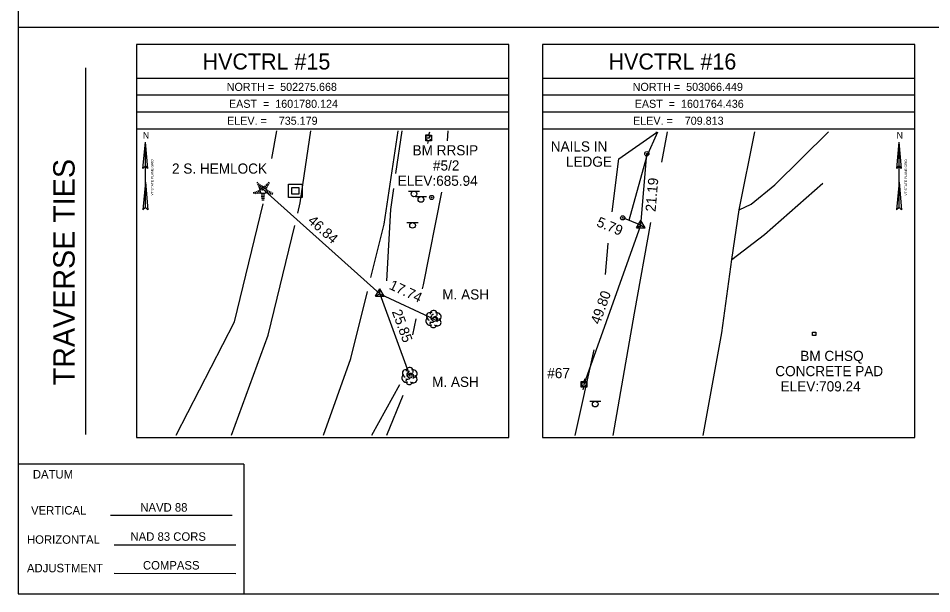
# Model space of a CAD drawing. Extents: x 1598730 to 1599370, y 501440 to 502728.
# Drawn here: x 1598729.5 to 1598999.5, y 501873 to 502042.9 of the extents above; entities that cross this region are included whole.
import ezdxf

# ---------------------------------------------------------------- set-up
doc = ezdxf.new("R2010")
doc.units = 0
for name, color, linetype in [('C_C', 7, 'Continuous'), ('CBP', 7, 'Continuous'), ('CPBM', 7, 'Continuous'), ('CPSM', 7, 'Continuous'), ('Default', 7, 'Continuous'), ('DS', 7, 'Continuous'), ('L_C', 7, 'Continuous'), ('LABL', 7, 'Continuous'), ('LARO', 7, 'Continuous'), ('LAWA', 7, 'Continuous'), ('LTC', 7, 'Continuous'), ('LTD', 7, 'Continuous'), ('LW', 7, 'Continuous'), ('NBL1', 7, 'Continuous'), ('NBL2', 7, 'Continuous'), ('NNA_P', 7, 'Continuous'), ('PET', 7, 'Continuous'), ('RDF', 7, 'Continuous'), ('RGR', 7, 'Continuous'), ('SSGN', 7, 'Continuous'), ('U_C', 7, 'Continuous'), ('UP', 7, 'Continuous'), ('UPGW', 7, 'Continuous')]:
    doc.layers.add(name, color=color, linetype=linetype)

msp = doc.modelspace()

# ---------------------------------------------------------------- linework, layer by layer
at = {"layer": 'CBP'}
for centre, radius in [((1598915.32, 502002.92), 0.625), ((1598915.32, 502002.92), 0.0833), ((1598801.5, 501992.81), 0.625), ((1598801.5, 501992.81), 0.0833), ((1598908.2, 501984), 0.625), ((1598908.2, 501984), 0.0833), ((1598852.47, 501954.04), 0.625), ((1598852.47, 501954.04), 0.0833), ((1598845.28, 501937.29), 0.625), ((1598845.28, 501937.29), 0.0833), ((1598896.76, 501934.9), 0.625), ((1598896.76, 501934.9), 0.0833)]:
    msp.add_circle(centre, radius, dxfattribs=at)
at = {"layer": 'CPBM'}
for p, q in [((1598850.03, 502007.56), (1598850.03, 502008.56)), ((1598850.03, 502008.56), (1598851.03, 502008.56)), ((1598851.03, 502007.56), (1598850.03, 502007.56)), ((1598850.53, 502008.06), (1598850.53, 502008.06)), ((1598850.53, 502008.06), (1598850.53, 502008.06)), ((1598851.03, 502008.56), (1598851.03, 502007.56)), ((1598964.3, 501949.26), (1598964.3, 501950.26)), ((1598964.3, 501950.26), (1598965.3, 501950.26)), ((1598965.3, 501949.26), (1598964.3, 501949.26)), ((1598964.8, 501949.76), (1598964.8, 501949.76)), ((1598964.8, 501949.76), (1598964.8, 501949.76)), ((1598965.3, 501950.26), (1598965.3, 501949.26))]:
    msp.add_line(p, q, dxfattribs=at)
at = {"layer": 'CPSM'}
for p, q in [((1598912.3, 501981.07), (1598913.55, 501983.23)), ((1598912.3, 501981.07), (1598913.55, 501981.79)), ((1598912.3, 501981.07), (1598914.8, 501981.07)), ((1598914.8, 501981.07), (1598913.55, 501983.23)), ((1598913.55, 501981.79), (1598913.55, 501983.23)), ((1598913.55, 501981.79), (1598913.55, 501981.79)), ((1598913.55, 501981.79), (1598914.8, 501981.07)), ((1598835.14, 501960.83), (1598836.39, 501963)), ((1598837.64, 501960.83), (1598836.39, 501963)), ((1598836.39, 501961.56), (1598836.39, 501963)), ((1598835.14, 501960.83), (1598836.39, 501961.56)), ((1598835.14, 501960.83), (1598837.64, 501960.83)), ((1598836.39, 501961.56), (1598836.39, 501961.56)), ((1598836.39, 501961.56), (1598837.64, 501960.83))]:
    msp.add_line(p, q, dxfattribs=at)
at = {"layer": 'Default'}
for p, q in [((1598913.55, 501981.79), (1598915.32, 502002.92)), ((1598801.5, 501992.81), (1598836.39, 501961.56)), ((1598913.55, 501981.79), (1598908.2, 501984)), ((1598896.76, 501934.9), (1598913.55, 501981.79)), ((1598836.39, 501961.56), (1598852.47, 501954.04)), ((1598836.39, 501961.56), (1598845.28, 501937.29))]:
    msp.add_line(p, q, dxfattribs=at)
at = {"layer": 'DS'}
for p, q in [((1598809.42, 501993.97), (1598813.42, 501993.97)), ((1598809.42, 501989.97), (1598809.42, 501993.97)), ((1598810.42, 501990.97), (1598810.42, 501992.97)), ((1598810.42, 501992.97), (1598812.42, 501992.97)), ((1598811.42, 501991.97), (1598811.42, 501991.97)), ((1598811.42, 501991.97), (1598811.42, 501991.97)), ((1598812.42, 501992.97), (1598812.42, 501990.97)), ((1598813.42, 501993.97), (1598813.42, 501989.97)), ((1598813.42, 501989.97), (1598809.42, 501989.97)), ((1598812.42, 501990.97), (1598810.42, 501990.97))]:
    msp.add_line(p, q, dxfattribs=at)
at = {"layer": 'LABL'}
for points in [[(1598905.07, 501985.81), (1598907.07, 502001.44), (1598918.17, 502009.21), (1598918.18, 502009.36)], [(1598903.15, 501967.25), (1598903.86, 501976.38), (1598903.88, 501976.5)], [(1598894.16, 501919.7), (1598899.79, 501945.01)]]:
    msp.add_lwpolyline(points, dxfattribs=at)
at = {"layer": 'LARO'}
msp.add_lwpolyline([(1598910.07, 501983.33), (1598915.36, 502002.07), (1598918.55, 502009.36)], dxfattribs=at)
at = {"layer": 'LAWA'}
for points in [[(1598804.51, 502001.49), (1598805.98, 502009.71)], [(1598776.17, 501919.87), (1598793.4, 501953.26), (1598801.93, 501988.12)], [(1598838.43, 501919.87), (1598843.28, 501931.63)]]:
    msp.add_lwpolyline(points, dxfattribs=at)
at = {"layer": 'LTC'}
for p, q in [((1598800.01, 501994.27), (1598800.36, 501994.53)), ((1598800.22, 501993.8), (1598800.75, 501994.19)), ((1598803.04, 501994.16), (1598803.59, 501993.76)), ((1598803.41, 501994.51), (1598803.83, 501994.21)), ((1598799.04, 501991.55), (1598799.19, 501991.08)), ((1598799.5, 501991.77), (1598799.71, 501991.11)), ((1598799.95, 501991.98), (1598800.22, 501991.15)), ((1598800.41, 501992.2), (1598800.74, 501991.18)), ((1598800.43, 501993.34), (1598801.13, 501993.85)), ((1598800.64, 501992.87), (1598801.52, 501993.51)), ((1598800.86, 501992.42), (1598801.87, 501993.15)), ((1598800.86, 501992.42), (1598801.25, 501991.22)), ((1598801.87, 501993.15), (1598802.87, 501992.43)), ((1598802.29, 501993.47), (1598803.1, 501992.88)), ((1598802.87, 501992.43), (1598802.48, 501991.22)), ((1598802.67, 501993.81), (1598803.34, 501993.32)), ((1598803.31, 501992.16), (1598802.97, 501991.12)), ((1598803.75, 501991.91), (1598803.47, 501991.02)), ((1598804.2, 501991.66), (1598803.96, 501990.93)), ((1598804.64, 501991.41), (1598804.46, 501990.83)), ((1598802.48, 501991.22), (1598801.25, 501991.22)), ((1598802.44, 501990.72), (1598801.3, 501990.72)), ((1598802.36, 501990.22), (1598801.37, 501990.22)), ((1598802.27, 501989.72), (1598801.44, 501989.72)), ((1598802.19, 501989.22), (1598801.52, 501989.22))]:
    msp.add_line(p, q, dxfattribs=at)
at = {"layer": 'LTD'}
for p, q in [((1598852.24, 501954.17), (1598852.24, 501954.17)), ((1598852.24, 501954.17), (1598852.24, 501954.17)), ((1598845.15, 501937.36), (1598845.15, 501937.36)), ((1598845.15, 501937.36), (1598845.15, 501937.36))]:
    msp.add_line(p, q, dxfattribs=at)
for centre in [(1598852.29, 501955.6), (1598845.2, 501938.79)]:
    msp.add_arc(centre, 1.05, 335.5272, 180.9563, dxfattribs=at)
for centre, major_axis, ratio, start_param, end_param in [((1598851.16, 501953.46), (0.58, -1.04), 0.959034, 3.141593, 6.283185), ((1598851.45, 501954.84), (1.21, -0.51), 0.895232, 1.570796, 4.712389), ((1598852.03, 501954.63), (-0.208, -0.792), 0.645439, 3.141593, 6.283185), ((1598852.74, 501954), (-0.5, 0.667), 0.989748, 3.141593, 6.283185), ((1598853.24, 501953.34), (-1.09, 0.79), 0.841452, 1.570796, 4.712389), ((1598853.28, 501954.75), (-1.14, -0.48), 0.949671, 1.570796, 4.712389), ((1598852.24, 501952.67), (0.26, 1.06), 0.942809, 1.570796, 4.712389), ((1598851.78, 501953.42), (-0.625, -0.083), 0.423636, 0, 3.141593), ((1598844.07, 501936.65), (0.58, -1.04), 0.959034, 3.141593, 6.283185), ((1598844.36, 501938.02), (1.21, -0.51), 0.895232, 1.570796, 4.712389), ((1598844.94, 501937.82), (-0.208, -0.792), 0.645439, 3.141593, 6.283185), ((1598845.65, 501937.19), (-0.5, 0.667), 0.989748, 3.141593, 6.283185), ((1598846.15, 501936.52), (-1.09, 0.79), 0.841452, 1.570796, 4.712389), ((1598846.19, 501937.94), (-1.14, -0.48), 0.949671, 1.570796, 4.712389), ((1598845.15, 501935.86), (0.26, 1.06), 0.942809, 1.570796, 4.712389), ((1598844.69, 501936.61), (-0.625, -0.083), 0.423636, 0, 3.141593)]:
    msp.add_ellipse(centre, major_axis=major_axis, ratio=ratio, start_param=start_param, end_param=end_param, dxfattribs=at)
at = {"layer": 'LW'}
for points in [[(1598856.43, 502006.72), (1598856.63, 502009.71)], [(1598849.02, 501963.01), (1598849.27, 501964.23), (1598854.76, 501991.59)], [(1598846.14, 501949.41), (1598847.15, 501954.18)], [(1598834.08, 501919.87), (1598842.33, 501934.81)]]:
    msp.add_lwpolyline(points, dxfattribs=at)
at = {"layer": 'NBL1'}
msp.add_lwpolyline([(1598729.53, 501873.01), (1599369.53, 501873.01), (1599369.53, 502293.01), (1598729.53, 502293.01)], close=True, dxfattribs=at)
at = {"layer": 'NBL2'}
for p, q in [((1598729.53, 502040.34), (1599369.53, 502040.34)), ((1598749.53, 501920.01), (1598749.53, 502028.34)), ((1598874.53, 502025.18), (1598764.53, 502025.18)), ((1598994.53, 502025.18), (1598884.53, 502025.18)), ((1598874.53, 502020.18), (1598764.53, 502020.18)), ((1598994.53, 502020.18), (1598884.53, 502020.18)), ((1598874.53, 502015.18), (1598764.53, 502015.18)), ((1598994.53, 502015.18), (1598884.53, 502015.18)), ((1598874.53, 502010.18), (1598764.53, 502010.18)), ((1598994.53, 502010.18), (1598884.53, 502010.18)), ((1598796.2, 501911.26), (1598729.53, 501911.26)), ((1598796.2, 501911.26), (1598796.2, 501873.01)), ((1598796.2, 501911.26), (1598796.2, 501873.01)), ((1598756.77, 501896.24), (1598792.77, 501896.21)), ((1598757.88, 501887.47), (1598793.88, 501887.47)), ((1598757.88, 501879.03), (1598793.88, 501879))]:
    msp.add_line(p, q, dxfattribs=at)
for points in [[(1598764.53, 501919.18), (1598874.53, 501919.18), (1598874.53, 502035.18), (1598764.53, 502035.18)], [(1598884.53, 501919.18), (1598994.53, 501919.18), (1598994.53, 502035.18), (1598884.53, 502035.18)]]:
    msp.add_lwpolyline(points, close=True, dxfattribs=at)
at = {"layer": 'NNA_P'}
for p, q in [((1598766.4, 501998.59), (1598767.1, 502006.38)), ((1598767.1, 501987.01), (1598767.1, 502006.38)), ((1598767.79, 501998.59), (1598767.1, 502006.38)), ((1598989.2, 501998.59), (1598989.89, 502006.38)), ((1598989.89, 501987.01), (1598989.89, 502006.38)), ((1598990.58, 501998.59), (1598989.89, 502006.38)), ((1598766.4, 501998.59), (1598767.1, 501999.36)), ((1598767.79, 501998.59), (1598767.1, 501999.36)), ((1598989.2, 501998.59), (1598989.89, 501999.36)), ((1598990.59, 501998.59), (1598989.89, 501999.36)), ((1598767.1, 501994.53), (1598766.38, 501986.37)), ((1598767.1, 501994.53), (1598767.82, 501986.37)), ((1598989.89, 501994.53), (1598989.17, 501986.37)), ((1598989.89, 501994.53), (1598990.61, 501986.37)), ((1598767.1, 501987.01), (1598766.38, 501986.37)), ((1598767.1, 501987.01), (1598767.82, 501986.37)), ((1598989.89, 501987.01), (1598989.17, 501986.37)), ((1598989.89, 501987.01), (1598990.61, 501986.37))]:
    msp.add_line(p, q, dxfattribs=at)
at = {"layer": 'PET'}
for points in [[(1598812.16, 501985.37), (1598812.9, 501988.42), (1598816.01, 502009.71)], [(1598833.74, 501966.35), (1598837.66, 501982.13), (1598841.8, 502009.71)], [(1598919.74, 502000.48), (1598921.46, 502009.36)], [(1598931.96, 501919.7), (1598937.53, 501950.07), (1598940.47, 501971.7), (1598942.65, 501986.37), (1598947.22, 502009.36)], [(1598792.52, 501919.87), (1598803.42, 501949.33), (1598811.27, 501981.71)], [(1598905.37, 501919.7), (1598911.66, 501955.81), (1598916.49, 501982.64)], [(1598819.79, 501919.87), (1598827.8, 501942.47), (1598832.73, 501962.3)]]:
    msp.add_lwpolyline(points, dxfattribs=at)
at = {"layer": 'RDF'}
for points in [[(1598942.65, 501986.37), (1598946.13, 501988.05), (1598953.17, 501993.74), (1598969.02, 502009.36)], [(1598940.47, 501971.7), (1598950.1, 501979.09), (1598967.34, 501994.29)]]:
    msp.add_lwpolyline(points, dxfattribs=at)
at = {"layer": 'RGR'}
for points in [[(1598841.16, 501997.13), (1598842.96, 502009.71)], [(1598838.52, 501965.45), (1598839.63, 501986.5), (1598840.51, 501992.62)]]:
    msp.add_lwpolyline(points, dxfattribs=at)
at = {"layer": 'SSGN'}
for p, q in [((1598844.84, 501991.91), (1598848.17, 501991.91)), ((1598846.49, 501991.07), (1598846.49, 501991.07)), ((1598846.91, 501990.27), (1598850.24, 501990.27)), ((1598848.55, 501989.43), (1598848.55, 501989.43)), ((1598844.43, 501982.61), (1598847.76, 501982.61)), ((1598846.07, 501981.78), (1598846.07, 501981.78)), ((1598898.43, 501929.85), (1598901.76, 501929.85)), ((1598900.07, 501929.01), (1598900.07, 501929.01))]:
    msp.add_line(p, q, dxfattribs=at)
for centre in [(1598846.49, 501991.07), (1598848.55, 501989.43), (1598846.07, 501981.78), (1598900.07, 501929.01)]:
    msp.add_circle(centre, 0.833, dxfattribs=at)
at = {"layer": 'UP'}
for p, q in [((1598849.97, 502006.76), (1598849.97, 502008.42)), ((1598849.97, 502008.42), (1598851.63, 502008.42)), ((1598851.05, 502009.26), (1598850.8, 502008.42)), ((1598850.8, 502007.59), (1598850.8, 502007.59)), ((1598851.63, 502008.42), (1598851.63, 502006.76)), ((1598851.63, 502006.76), (1598849.97, 502006.76)), ((1598850.55, 502005.92), (1598850.8, 502006.76)), ((1598895.88, 501934.01), (1598895.88, 501935.67)), ((1598895.88, 501935.67), (1598897.55, 501935.67)), ((1598896.97, 501936.51), (1598896.72, 501935.67)), ((1598896.72, 501934.84), (1598896.72, 501934.84)), ((1598897.55, 501935.67), (1598897.55, 501934.01)), ((1598897.55, 501934.01), (1598895.88, 501934.01)), ((1598896.47, 501933.17), (1598896.72, 501934.01))]:
    msp.add_line(p, q, dxfattribs=at)
for centre in [(1598850.8, 502007.59), (1598896.72, 501934.84)]:
    msp.add_circle(centre, 0.833, dxfattribs=at)
at = {"layer": 'UPGW'}
for radius in [0.625, 0.0833]:
    msp.add_circle((1598851.74, 501990.01), radius, dxfattribs=at)

# ---------------------------------------------------------------- texts
at = {"layer": 'C_C'}
for s, p in [('NAILS IN', (1598886.93, 502003.59)), ('LEDGE', (1598891.41, 501999.09)), ('BM CHSQ', (1598960.68, 501941.75)), ('CONCRETE PAD', (1598953.3, 501937.25)), ('ELEV:709.24', (1598954.87, 501932.75))]:
    msp.add_text(s, height=3, dxfattribs=at).set_placement(p)
at = {"layer": 'Default'}
for s, rotation, p in [('21.19', 85.1968, (1598917.9, 501985.7)), ('46.84', 318.15, (1598814.89, 501982.83)), ('5.79', 337.5488, (1598900.23, 501981.65)), ('17.74', 334.9519, (1598838.92, 501963.1)), ('49.80', 70.2998, (1598901.41, 501952.34)), ('25.85', 290.111, (1598839.91, 501956.31))]:
    msp.add_text(s, height=3, rotation=rotation, dxfattribs=at).set_placement(p)
at = {"layer": 'L_C'}
for s, p in [('2 S. HEMLOCK', (1598774.97, 501997.05)), ('M. ASH', (1598854.86, 501959.89)), ('M. ASH', (1598851.85, 501934.08))]:
    msp.add_text(s, height=3, dxfattribs=at).set_placement(p)
at = {"layer": 'LTC'}
msp.add_text('.', height=1.04, rotation=270, dxfattribs=at).set_placement((1598801.76, 501992.17))
at = {"layer": 'NBL2'}
for s, height, p in [('     HVCTRL #15    ', 4.75, (1598775.18, 502027.8)), ('     HVCTRL #16    ', 4.75, (1598895.18, 502027.8)), ('NORTH =  502275.668 ', 2.375, (1598791.15, 502021.49)), ('NORTH =  503066.449 ', 2.375, (1598911.15, 502021.49)), ('EAST  =  1601780.124', 2.375, (1598791.81, 502016.49)), ('EAST  =  1601764.436', 2.375, (1598911.74, 502016.49)), ('ELEV. =    735.179  ', 2.375, (1598791.26, 502011.49)), ('ELEV. =    709.813  ', 2.375, (1598911.26, 502011.49)), ('DATUM', 2.5, (1598733.85, 501907.03)), ('  NAVD 88 ', 2.5, (1598763.75, 501897.25)), ('HORIZONTAL', 2.5, (1598732.11, 501887.76)), ('NAD 83 CORS', 2.5, (1598762.71, 501888.64)), ('ADJUSTMENT', 2.5, (1598732.11, 501879.33)), ('  COMPASS ', 2.5, (1598764.53, 501880.15))]:
    msp.add_text(s, height=height, dxfattribs=at).set_placement(p)
for s, height, rotation, p in [('TRAVERSE TIES', 6.3332, 90, (1598746.2, 501934.56)), ('VERTICAL', 2.5, 0.1439, (1598733.31, 501896.36))]:
    msp.add_text(s, height=height, rotation=rotation, dxfattribs=at).set_placement(p)
at = {"layer": 'NNA_P'}
for p in [(1598766.34, 502007.4), (1598989.13, 502007.4)]:
    msp.add_text('N', height=1.97, dxfattribs=at).set_placement(p)
for p in [(1598769.45, 501990.57), (1598992.24, 501990.57)]:
    msp.add_text('VT STATE PLANE GRID', height=0.7, rotation=90.0204, dxfattribs=at).set_placement(p)
at = {"layer": 'U_C'}
for s, p in [('BM RRSIP', (1598846.08, 502002.46)), ('#5/2', (1598852.11, 501997.96)), ('ELEV:685.94', (1598841.69, 501993.46)), ('#67', (1598885.9, 501936.65))]:
    msp.add_text(s, height=3, dxfattribs=at).set_placement(p)

doc.saveas('drawing.dxf')
